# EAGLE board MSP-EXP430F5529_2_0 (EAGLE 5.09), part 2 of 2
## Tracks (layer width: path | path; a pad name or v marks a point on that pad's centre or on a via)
5529_LDO  (via drill 0.3, 0.56)
  Top 0.305: 88.17,30.01 U1.66
  Top 0.61: 88.17,30.01 89.12,30.01 89.84,29.29 C5.1 90.68,26.16 v91.19,26.67 90.42,25.91 C9.1 91.94,24.22 C7.1
  PWR 1.016: v34.04,46.74 34.04,42.42 49.02,27.43 52.83,27.43 58.93,21.34 70.61,21.34 72.14,19.81 88.39,19.81 91.19,22.61 v91.19,26.67
  Bottom 0.254: S4.1 99.82,69.85 99.82,61.72 99.06,60.96 98.04,60.96 95.76,58.67 95.76,37.59 97.54,35.81 97.54,27.69 96.27,26.42 91.44,26.42 v91.19,26.67
  Bottom 1.016: v34.04,46.74 21.08,59.69 18.03,59.69 17.27,60.45 17.27,65.53 JP8.1
5529_VBUS  (via drill 0.3, 0.56)
  Top 0.305: U1.65 86.36,29.52 86.16,29.52 | 30.01,67.95 R19.2 | 29.98,65.86 U4.8
  Top 0.406: 85.39,29.52 86.16,29.52 | 29.9,65.86 29.98,65.86
  Top 0.61: v85.09,29.21 85.39,29.52 | 93.31,56.39 C34.1 95.25,56.22 | v28.96,66.8 29.9,65.86 | 95.25,56.22 C33.1 | v95,57.91 95,56.48 95.25,56.22
  Top 0.813: 28.87,66.8 30.01,67.95 | C27.2 27.93,65.86 28.87,66.8 | 28.87,66.8 v28.96,66.8
  PWR 0.61: 75.18,76.96 76.71,78.49 82.04,78.49 82.8,77.72 81.03,75.95 76.2,75.95 75.18,76.96
  PWR 1.016: v34.54,74.42 38.86,74.42 41.4,76.96 75.18,76.96 | 82.8,77.72 91.69,77.72 94.49,74.93 94.49,65.53 96.77,63.25 JP15.1
  Bottom 0.61: v85.09,29.21 85.09,32.26 87.88,35.05 88.9,35.05 92.71,38.86 94.64,38.86 95,39.22 v95,57.91 95,59.69 97.79,62.48 JP15.1
  Bottom 1.016: v28.96,66.8 34.54,72.39 v34.54,74.42
A5  (via drill 0.3)
  Top 0.254: v99.06,40.89 98.3,41.66 88.9,41.66 87.38,40.13 85.85,40.13 85.6,40.39 84.84,40.39 84.51,40.06 U1.2 | v102.11,37.85 102.11,20.83 108.46,14.48 108.46,8.3 POT1.2
  Bottom 0.254: v102.11,37.85 v99.06,40.89
ACCEL_CS
  Top 0.254: U1.42 76.01,26.35 75.69,26.67 74.93,26.67 72.89,24.63 U2.7
ACCEL_INT
  Top 0.254: U1.34 74.9,30.51 75.69,29.72 75.69,28.19 72.63,25.13 U2.8
ACCEL_PWR  (via drill 0.3)
  Top 0.305: U1.43 76.51,23.17 74.93,21.59 69.6,21.59 68.33,22.86 v68.33,23.62 68.83,24.13 U2.3 | v68.33,25.65 68.85,25.13 U2.1
  Bottom 0.305: v68.33,23.62 67.82,23.11 C20.1 C21.1 v68.33,25.65
ACCEL_SCK  (via drill 0.3)
  Top 0.254: U1.36 74.89,29.51 v74.93,29.46 | v74.68,23.37 73.66,23.37 73.39,23.63 U2.5
  Bottom 0.254: v74.93,29.46 74.42,29.46 73.66,28.7 73.66,25.91 74.68,24.89 v74.68,23.37
ACCEL_SIMO  (via drill 0.3)
  Top 0.254: v73.91,24.13 U2.6
  Top 0.305: U1.40 72.72,27.51 72.39,27.18 72.39,26.92 72.64,26.67 v72.9,26.67
  Bottom 0.254: v72.9,26.67 72.9,25.15 v73.91,24.13
ACCEL_SOMI
  Top 0.254: U1.41 75.51,22.94 74.68,22.1 69.85,22.1 69.09,22.86 69.09,23.37 69.35,23.63 U2.4
ALT_LDO  (via drill 0.3)
  Top 0.406: U4.1 30.01,61.26 v29.46,60.71
  Top 0.813: v29.46,60.71 28.02,60.71 C28.2
  Bottom 1.016: SW1.1 6.86,76.2 12.45,70.61 20.83,70.61 JP8.3 24.13,66.04 v29.46,60.71
AVCC  (via drill 0.3)
  Top 0.305: U1.11 80.01,38.1
  Top 0.406: 80.01,38.1 80.52,37.59 85.85,37.59 v86.11,37.85
  Bottom 0.406: v86.11,37.85 87.31,39.05 C13.1 | C13.1 87.38,39.37 R2.1 | C50.+ 88.57,40.24 C13.1
BRXD  (via drill 0.3)
  Top 0.254: R35.2 9.91,49.28 v7.87,51.31 | U8.10 5.7,55.77 v5.59,55.88 4.06,55.88 2.66,57.28 J17.6
  Bottom 0.254: v7.87,51.31 7.87,53.59 v5.59,55.88
BRXDI  (via drill 0.3)
  Top 0.254: v13.72,43.69 13.75,43.72 U7.35 13.75,46.19 13.46,46.48 10.92,46.48 9.91,47.5 R35.1 | v9.14,24.38 8.89,24.13 8.89,22.35 6.34,19.81 U10.32 5.35,19.32 3.3,17.27 R45.1
  Bottom 0.254: v13.72,43.69 11.94,43.69 8.38,40.13 8.38,25.65 9.14,24.89 v9.14,24.38
BTXD  (via drill 0.3)
  Top 0.254: R36.2 10.92,49.78 8.64,52.07 6.86,52.07 5.72,50.93 J17.1 | v4.83,55.12 U8.11
  Bottom 0.254: v4.83,55.12 4.83,53.8 4.83,52.83 2.93,50.93 J17.1
BTXDI  (via drill 0.3)
  Top 0.254: R36.1 10.92,47.5 11.43,46.99 13.97,46.99 v14.22,46.74 14.25,46.71 U7.34 | v8.13,24.38 8.13,22.61 6.13,20.61 U10.31 4.6,20.61 4.32,20.32 4.32,19.3 2.29,17.27 R44.1
  Bottom 0.254: v14.22,46.74 7.87,40.39 7.87,25.4 8.13,25.15 v8.13,24.38
CB0  (via drill 0.3)
  Top 0.254: U1.77 86.31,35.51 85.85,35.05 83.82,35.05 82.8,36.07 v82.8,36.32 | PAD1.1 v41.4,12.19
  Bottom 0.254: v82.8,36.32 82.8,35.05 82.04,34.29 75.35,34.29 70.1,29.04 70.1,18.24 69.39,17.53 45.72,17.53 44.11,15.91 R14.2
  Bottom 0.305: R14.2 41.66,12.45 v41.4,12.19
CB1  (via drill 0.3)
  Top 0.254: U1.78 86.05,36.01 85.6,35.56 84.07,35.56 83.57,36.07 v83.57,36.83 | PAD2.1 v52.58,12.19
  Bottom 0.254: v83.57,36.83 83.57,35.05 82.3,33.78 75.69,33.78 70.61,28.7 70.61,17.93 69.7,17.02 56.39,17.02 55.37,16 55.37,12.53 R15.2
  Bottom 0.305: R15.2 52.83,12.45 v52.58,12.19
CB2  (via drill 0.3)
  Top 0.254: U1.79 85.78,36.51 85.34,36.07 84.58,36.07 v84.33,36.32 | PAD3.1 v63.75,12.19
  Bottom 0.254: v84.33,36.32 84.33,35.05 82.55,33.27 75.95,33.27 71.12,28.45 71.12,17.02 69.34,15.24 67.82,15.24 66.46,13.88 R16.1
  Bottom 0.305: R16.1 64.01,12.45 v63.75,12.19
CB3  (via drill 0.3)
  Top 0.254: U1.80 85.27,37.01 v85.09,36.83 | PAD4.1 v74.93,12.19
  Bottom 0.254: v85.09,36.83 85.09,35.01 82.85,32.77 76.2,32.77 71.63,28.19 71.63,17.02 74.93,13.72 v74.93,12.19 | 77.72,12.53 R12.2 77.22,12.45
  Bottom 0.305: 77.22,12.45 75.18,12.45 v74.93,12.19
CB4  (via drill 0.3)
  Top 0.254: 85.01,39.29 85.34,39.62 85.6,39.62 85.85,39.37 v85.85,38.86 85.34,38.86 85.09,39.12 85.06,39.08 U1.1 | v86.11,12.19 PAD5.1
  Bottom 0.254: v85.85,38.86 85.09,38.1 85.09,37.85 85.85,37.08 85.85,35.01 83.1,32.26 76.45,32.26 72.14,27.94 72.14,17.48 73.62,16 85.6,16 86.11,15.49 v86.11,12.19
  Bottom 0.305: R13.2 86.36,12.45 v86.11,12.19
CBOUT  (via drill 0.3)
  Top 0.254: v46.99,12.95 v58.17,12.95 v69.34,12.95 v80.52,12.95 v91.69,12.95 | U1.27 61.69,34.01 54.61,26.92 54.61,18.54 57.15,16 v58.17,16
  Bottom 0.254: R14.1 45.81,12.53 46.57,12.53 v46.99,12.95 | 56.98,12.53 R15.1 57.66,12.45 v58.17,12.95 v58.17,16 | R16.2 68.16,12.53 68.92,12.53 v69.34,12.95 | 79.34,12.53 R12.1 80.01,12.45 v80.52,12.95 | R13.1 90.51,12.53 91.27,12.53 v91.69,12.95
CLK3410  (via drill 0.3)
  Top 0.254: U7.49 5.2,43.82 v5.08,43.94 | v1.52,21.34 R49.2
  Bottom 0.254: v5.08,43.94 5.08,33.53 1.52,29.97 v1.52,21.34
D1A  (via drill 0.3)
  Top 0.254: 25.15,27.69 25.14,27.69 U5.4 | U5.3 24.64,28.19 25.27,27.56
  Top 0.61: v30.99,24.13 28.7,24.13 25.27,27.56 25.15,27.69
  Bottom 0.406: 31.08,24.03 v30.99,24.13
  Bottom 0.61: U3.1 31.08,24.03
D1B  (via drill 0.3, 0.56)
  Top 0.254: U5.7 25.14,33.52 25.91,34.29 25.71,34.29 24.64,33.21 U5.8
  Top 0.61: 25.91,34.29 27.94,34.29 v39.62,22.61 | U3.14 59.87,20.32 v57.15,20.32
  Bottom 0.61: v57.15,20.32 41.91,20.32 v39.62,22.61
DVCC  (via drill 0.56, 1.4)
  Top 0.254: R1.2 89.32,46.48 v87.88,46.48
  Top 0.305: 80.26,24.13 80.01,24.38 80.01,24.64 U1.50 80.01,27.94 | 76.51,38.16 U1.18
  Top 0.406: v81.28,23.88 80.52,23.88 80.26,24.13 | v78.49,29.46 80.01,27.94 | 76.51,38.16 76.51,37.79 v76.71,37.59
  PWR 0.813: JP6.2 29.97,78.23 29.21,78.99 26.16,78.99 22.1,74.93 22.1,71.37 20.83,70.1 18.54,70.1 17.02,68.58 17.02,67.06 21.59,62.48 JP11.2 21.59,56.64 JP16.9
  Bottom 0.406: v78.49,29.46 78.49,27.51 C15.+ 78.56,25.29 C16.2 | C12.1 80.84,24.32 v81.28,23.88 | R2.2 91.19,39.37 v92.2,40.39 92.37,40.55 C11.2 | v87.88,46.48 C10.+
  Bottom 0.61: 55.37,52.58 55.37,55.12 54.86,55.63 | 52.07,55.63 52.58,55.12 52.58,53.09 53.09,52.58
  Bottom 1.016: 54.86,55.63 52.07,55.63 48.01,55.63 40.89,62.74 40.89,70.87 35.05,76.71 JP6.2 | 53.09,52.58 55.37,52.58 62.61,45.34 | 62.61,45.34 63.25,44.7 v63.25,44.2 | v64.01,45.47 62.74,45.47 62.61,45.34
  Bottom 1.27: JP6.2 31.24,76.71 v34.04,79.5
  pour PWR (isolate 0.305): 85.6,25.15 83.05,22.1 78.5,22.1 61.72,38.88 61.72,45.15 63.31,46.74 64.77,46.74 71.88,39.62 77.41,39.62 arc-90 77.98,39.06 77.98,38.92 arc90 78.55,38.35 80.71,38.35 arc90 81.28,38.92 81.28,41.91 87.38,48.01 93.98,48.01 93.98,39.22 88.79,34.04 86.68,34.04 arc90 85.6,32.96
DVCC_SW  (via drill 1.4)
  Top 1.27: SW1.7 4.73,72.14 7.11,72.14 11.43,76.45 11.43,78.99 12.45,80.01 23.11,80.01 v23.62,79.5
  Bottom 1.27: v23.62,79.5 24.64,79.5 JP6.1
EZ_D+
  Top 0.254: USB2.D+ 7.89,7.35 8.89,6.35 10.42,6.35 R43.1 11.69,5.34 12.95,6.6 12.95,7.62 11.95,8.63 U11.5
EZ_D-  (via drill 0.3)
  Top 0.254: U11.3 9.39,7.63 v9.14,7.87 | v15.24,12.7 R46.1
  Bottom 0.254: USB2.D- 6.6,8.26 6.6,9.4 7.37,10.16 8.64,10.16 9.14,9.65 v9.14,7.87 9.4,7.62 15.24,7.62 16.26,8.64 16.26,11.68 16,11.94 v15.24,12.7
EZ_VBUS
  Top 0.305: U11.1 8.23,8.63 USB2.VBUS
  Top 0.406: U9.6 U9.5 12.85,11.18 | 12.85,11.18 12.45,11.18 12.45,10.92 13.72,10.92 13.72,11.18 12.85,11.18 | TP9.1 10.67,11.18 11.18,11.68 C43.2
  Top 0.813: USB2.VBUS 7.89,9.16 TP9.1 12.45,11.18
EZ_VCC  (via drill 0.3, 0.56)
  Top 0.254: 4.6,35.31 6.35,35.31 7.11,34.54 | 7.11,32.92 7.11,34.54 | 7.11,34.54 7.25,34.54
  Top 0.305: U7.1 7.25,34.54 7.25,34.66 v6.86,35.05 6.37,35.54 U7.64
  Top 0.406: U9.7 11.61,10.08 v11.18,9.65 11.39,9.44 U9.8 | R33.2 R37.2 14.99,7.11 14.73,7.37 v14.73,9.65 | R40.2 C41.1 | C40.2 15.02,16.76 C41.1 | C41.1 13.46,17.53 v13.72,17.78 | v8.89,19.81 8.45,19.37 U10.3 8.45,17.34 R47.2 C47.2 | v2.29,14.99 R44.2 R45.2 | C48.2 C49.1 2.29,24.9 v3.3,25.91 3.8,25.41 U10.25 | U10.23 U10.24 6.62,26.91 v5.84,27.69 | v5.84,27.69 5.33,27.18 5.33,25.65 | 5.84,27.94 5.84,28.11 U12.8 3.51,28.49 R54.1 R53.1 | 5.84,27.94 v5.84,27.69 | 5.84,27.94 5.33,28.45 | C42.1 4.09,34.01 v4.06,34.04 | R39.2 16.76,21.85 v16.51,22.1 15.76,22.85 R28.2 | v5.84,52.58 6.43,53.17 U8.14 | R30.2 v16,49.78
  Top 0.813: v11.18,9.65 v14.73,9.65
  Top 1.016: SW1.2 SW1.6 v2.8,72.65 v2.79,72.64
  pour PWR (isolate 0.406): 0.76,0.76 0.76,77.22 8.13,77.22 8.13,58.17 17.53,58.17 17.53,0.76
GND  (via drill 0.3, 0.56, 1.4)
  Top 0.305: U1.19 76.01,40.2 v76.2,40.39 | R21.1 25.56,38.19 C30.1 | v6.86,36.83 6.57,36.54 | v76.96,27.43 78.49,27.43 79.51,26.4 U1.49 79.5,23.37 79.76,23.11 80.01,23.11 | 5.42,36.32 U7.62 U7.63 | U4.2 30.66,63.49 U4.PP@2 | 28.96,64.26 U4.PP@1 | U4.PP@1 33.27,64.26 | U4.PP@1 U4.TH@2 | v85.85,27.43 85.93,27.51 U1.61 | C5.2 87.96,27.36 87.81,27.51 U1.61 | U4.PP@4 31.31,65.04 U4.6 31.31,66.73 v30.99,67.06 30.66,66.73 U4.7 30.66,65.04 U4.PP@5 | U2.2 v68.08,24.63 v68.07,24.64 | U4.4 31.96,63.39 U4.PP@3 | U1.14 78.51,38.13 77.98,37.59 v77.72,37.59 | U1.68 84.6,31.01 v84.07,30.48 | C19.1 50.55,61.72 | U1.61 | 6.38,36.3 6.48,36.4 6.48,36.45 | U5.5 25.64,31.15 U5.P$3
  Top 0.406: v4.32,12.95 4.06,13.21 R48.1 | C43.1 9.14,12.45 v8.89,12.7 | U12.4 U12.1 12.07,29.59 | U10.18 11.65,25.18 v11.68,25.15 | U10.15 13.95,25.89 v14.22,26.16 | C37.2 v15.76,25.9 v15.75,25.91 | U10.8 12.45,19.3 v11.43,20.32 | U9.4 U9.3 | C45.1 11.68,3.3 v11.94,3.05 | U10.28 6.5,23.01 v6.6,23.11 | C48.1 v3.29,22.36 v3.3,22.35 | R51.2 3.29,19.31 3.3,19.3 v2.79,18.8 | X1.A 59,66.22 | v69.34,77.98 RF2.2 | C34.2 93.56,54.52 | 6.35,36.32 5.42,36.32 | U12.7 4.39,29.14 v4.32,29.21 | U8.7 13.89,57.07 v13.97,57.15 11.43,57.15 v11.18,56.9 11.94,56.9 12.19,57.15 12.7,57.15 | v17.78,17.53 15.77,17.53 C44.2 | C38.2 3.06,45.72 v1.78,45.72
  Top 0.61: 6.35,36.32 6.48,36.45 v6.86,36.83 | 50.55,61.72 50.29,61.98 v50.29,62.99
  Top 0.813: 4.65,36.3 6.38,36.3 | v103.89,58.42 107.19,58.42 J1.9
  GND 0.813: J1.9 107.19,58.42 v103.89,58.42 | v34.29,1.27 28.7,1.27 28.19,1.78 v28.19,3.3
  other vias: 1.52,49.53 8.38,47.24 12.45,49.53 1.52,32.26 13.21,30.73 16.51,13.21 14.73,6.1 28.19,10.41 28.19,6.86 22.35,24.13 25.65,39.62 35.05,60.2 62.99,55.63 43.69,65.53 91.44,50.04 97.79,72.14 99.31,44.96 100.84,54.36 60.45,43.18 22.35,32 28.7,31.75 4.06,24.64 61.95,19.99 65.28,24.38 32,34.29 9.14,78.99 23.37,70.87 34.04,64.26 33.78,67.31 26.42,58.67 6.6,64.26 2.03,66.04 23.11,39.62 9.91,21.34 16,28.19 15.24,11.18 16.26,46.74 16.51,55.63 32.77,20.07 39.88,25.91 52.07,24.64 49.02,16.51 41.4,16.51 96.52,7.62 97.79,2.54 102.62,18.54 97.54,21.08 88.9,37.59 93.47,44.45 56.9,46.99 60.96,52.07 38.35,56.64 36.32,46.74 61.98,78.49 38.1,60.71 33.27,75.18 93.73,79.5 92.46,68.58 109.47,41.15 57.4,26.16 1.52,1.52 1.52,79.76 110.24,79.76 110.24,1.52 36.32,79.76 6.86,38.35 70.87,80.01 34.29,25.15 100.58,50.04 105.41,70.36 87.88,44.96 49.28,42.67 84.58,16.76 11.68,6.6 10.67,29.46 41.91,58.67 101.09,75.69 101.85,67.56 93.22,57.4 80.52,22.1 72.39,45.47 93.73,53.09 97.79,12.7 90.17,18.29 60.96,58.67 54.61,62.99 63.5,75.69 64.26,70.87 57.66,62.99 28.19,64.52 28.19,69.09 11.94,74.42 18.54,36.83 88.39,53.09 68.55,27.1 72.87,22.78 3.56,57.91
  pour GND (isolate 0.406, rank 2): 0.76,0.76 0.76,80.52 111,80.52 111,61.21 104.9,61.21 104.9,55.88 102.62,55.88 102.62,41.91 111,41.91 111,20.57 109.22,20.57 109.22,12.45 111,12.45 111,0.76 95.25,0.76 95.25,14.73 29.21,14.73 29.21,0.76
  pour Top (isolate 0.406, rank 2): 0.76,0.76 0.76,80.52 111,80.52 111,61.21 104.9,61.21 104.9,55.88 102.62,55.88 102.62,41.91 111,41.91 111,20.57 109.22,20.57 109.22,12.45 111,12.45 111,0.76
  pour Bottom (isolate 0.406, rank 2): 0.76,0.76 0.76,80.52 111,80.52 111,61.21 104.9,61.21 104.9,55.88 102.62,55.88 102.62,41.91 111,41.91 111,20.57 109.22,20.57 109.22,12.45 111,12.45 111,0.76 99.82,0.76 99.82,15.24 29.21,15.24 29.21,0.76
  pour Bottom (isolate 0.406, hatched): 28.96,0.76 28.96,15.49 100.08,15.49 100.08,0.76
HTCK
  Top 0.254: U7.57 3.73,39.04 2.29,37.59 TP12.1
HTDI
  Top 0.254: U7.55 3.39,40.04 2.29,41.15 TP14.1
HTDO
  Top 0.254: U7.54 3.91,40.54 3.56,40.89 3.56,43.43 2.79,44.2 TP15.1
HTMS
  Top 0.254: U7.56 2.71,39.54 TP13.1
ISET
  Top 0.254: R21.2 23.11,34.29 23.64,33.77 U5.10
JTAG_PWR  (via drill 0.3)
  Top 1.016: SW1.8 SW1.4 6.73,68.2 15.24,59.69 15.37,59.69 20.83,59.69 32,48.51 v34.8,48.51
  PWR 1.016: v34.8,48.51 65.02,48.51 68.07,51.56 101.35,51.56 J1.2
JTAG_SENSE  (via drill 0.3)
  PWR 0.61: J1.4 104.39,51.05 104.39,54.1 103.12,55.37 87.88,55.37 85.6,53.09 67.31,53.09 64.52,50.29 v32.26,50.29
  Bottom 0.61: v32.26,50.29 32.26,50.8 24.13,58.93 JP11.1
LCD_BL_EN  (via drill 0.3)
  Top 0.254: v59.69,23.11 60.2,23.11 66.8,16.51 78.74,16.51 84.51,22.28 U1.59 | v36.58,23.37 27.94,23.37 24.38,26.92 23.96,26.92 R20.2 | R20.2 23.96,27.01 24.13,27.18 U5.2 | U5.1 23.64,27.25 R20.2
  Bottom 0.254: v36.58,23.37 59.44,23.37 v59.69,23.11
LCD_CS  (via drill 0.3)
  Top 0.254: v58.93,24.13 59.18,23.88 60.2,23.88 67.06,17.02 78.49,17.02 83.51,22.05 U1.57 | U3.28 32.35,55.44 R18.2
  Bottom 0.254: v58.93,24.13 58.93,35.05 46.74,47.24 38.02,47.24 U3.28
LCD_D/C  (via drill 0.3)
  Top 0.254: v60.45,26.16 60.96,25.65 60.96,24.64 67.56,18.03 77.98,18.03 82.51,22.57 U1.55
  Bottom 0.254: v60.45,26.16 60.45,36.07 47.24,49.28 41.07,49.28 U3.26
LCD_RST  (via drill 0.3)
  Top 0.254: v59.69,25.15 67.31,17.53 78.23,17.53 83.01,22.31 U1.56 | U3.27 34.71,55.27 R17.2
  Bottom 0.254: v59.69,25.15 59.69,35.56 46.99,48.26 39.55,48.26 U3.27
LDO_SEL
  Bottom 1.016: SW1.5 3.81,76.2 4.57,75.44 4.57,73.15 5.33,72.39 7.87,72.39 11.43,68.83 20.07,68.83 JP8.2
LFXTGND  (via drill 0.3)
  Top 0.254: Q1.P3 78.26,51.48 v78.26,43.56
  Top 0.305: v78.26,42.04 78.51,41.78 78.51,38.91
  Bottom 0.406: C4.2 C2.2 78.26,46.41 v78.26,43.56 v78.26,42.04
  pour Top (isolate 0.305, no thermals, hatched): 75.5,42.93 75.18,43.18 75.18,52.58 75.65,53.09 80.82,53.09 81.53,52.37 81.53,44.2 80.26,42.93
  pour Bottom (isolate 0.305): 77.98,38.61 77.98,40.39 75.18,43.18 75.18,52.58 75.65,53.09 80.82,53.09 81.53,52.37 81.53,41.66 80.26,40.39 80.26,38.61
  pour GND (isolate 0.305): 77.98,38.61 77.98,40.39 75.18,43.18 75.18,52.58 75.65,53.09 80.82,53.09 81.53,52.37 81.53,41.66 80.26,40.39 80.26,38.61
MSP_D+
  Top 0.254: R23.2 102.36,59.69 102.62,59.94 102.62,72.41 USB1.D+
  Bottom 0.305: U6.5 102.86,72.65 USB1.D+
MSP_D-  (via drill 0.3)
  Top 0.254: R22.2 97.79,53.85 98.3,54.36 v99.82,54.36
  Top 0.305: v101.09,74.68 101.6,74.68 103.38,76.45 104.9,76.45 106.17,75.18 106.17,73.91 105.12,72.86 USB1.D-
  Bottom 0.254: v99.82,54.36 99.82,58.17 104.39,62.74 104.39,70.87 105.07,71.54 USB1.D-
  Bottom 0.305: U6.3 100.7,74.28 v101.09,74.68
N$1  (via drill 0.3)
  Top 0.254: U7.47 7.75,46.11 8.13,46.48 v9.4,46.48 | v11.94,47.75 R29.1 R31.1
  Bottom 0.254: v9.4,46.48 10.67,46.48 v11.94,47.75
N$2  (via drill 0.3)
  Top 0.254: U7.46 8.25,44.07 8.38,43.94 8.75,43.94 | U7.43 9.75,44.04 9.65,43.94 8.89,43.94 | 8.75,43.94 U7.45 | 8.89,43.94 8.75,43.94 | 8.89,43.94 8.89,40.39 10.67,38.61 v13.46,38.61 | v15.49,39.12 15.57,39.04 U7.24 17.7,39.04 18.03,39.37 18.03,43.69 14.99,46.74 R32.1 R30.1
  Bottom 0.254: v13.46,38.61 14.99,38.61 v15.49,39.12
N$3
  Top 0.254: U10.27 4.5,23.81 4.32,23.62 4.32,21.59 4.06,21.34 R49.1 3.55,20.82 3.3,20.57 2.54,20.57 2.29,20.32 R51.1
N$4
  Top 0.254: U9.1 17.54,9.41 17.53,9.4 17.53,8.9 R38.2 R37.1
N$5
  Top 0.254: R41.1 4.77,17.21 D2.A 6.03,17.21 6.86,18.03 U10.1
N$6  (via drill 0.3)
  Top 0.254: U10.2 7.62,18.34 v7.62,19.56 | v5.84,14.22 5.59,14.48 D2.C
  Bottom 0.254: v5.84,14.22 6.35,14.22 7.62,15.49 v7.62,19.56
N$7
  Bottom 0.254: R10.2 70.52,9.99 71.97,8.55 LED7.A
N$8
  Bottom 0.254: R8.2 48.17,9.99 49.62,8.55 LED5.A
N$9
  Top 0.254: U10.12 15.13,22.21 15.75,21.59 15.75,21.09 R39.1
N$10
  Bottom 0.254: R9.2 59.35,9.99 60.79,8.55 LED6.A
N$11
  Bottom 0.254: R7.2 37,9.99 38.44,8.55 LED4.A
N$12
  Bottom 0.254: CON1.6 51.56,34.63 51.56,33.27 50.8,32.51 33.78,32.51 24.38,23.11 23.37,23.11 22.1,21.84 22.1,18.54 22.86,17.78 TP7.1
N$13
  Bottom 0.254: R11.2 81.7,9.99 83.14,8.55 LED8.A
N$14
  Top 0.305: U4.5 31.96,67.95 R19.1
N$15
  Top 0.254: U8.2 12.84,53.85 13.72,53.85 15.75,51.82 15.75,51.05 17.02,49.78 17.02,46.99 JP16.2
N$16  (via drill 0.3)
  Top 0.254: v6.6,25.91 9.65,25.91 10.92,24.64 10.92,23.88 13.39,21.41 U10.11 | v4.32,26.67 3.81,27.18 R52.2
  Bottom 0.254: v4.32,26.67 5.84,26.67 v6.6,25.91
N$17
  Top 0.254: R47.1 8.38,15.76 8.38,15.75 8.64,16 8.64,16.51 8.88,16.76 R50.2 9.4,17.27 9.25,17.42 U10.4
N$19
  Top 0.305: R33.1 16.76,5.58 16.26,5.08 16.26,3.83 LED9.A
N$20
  Bottom 0.254: CON1.4 54.23,32.64 53.34,31.75 33.78,31.75 23.37,21.34 TP5.1
N$21
  Top 0.254: LED3.A 31.5,2.79 32.35,1.94 R5.2
N$22
  Top 0.406: USB2.GND@1 2.29,11.52 R48.2
  Top 0.61: USB2.GND@2 USB2.GND@1
N$23
  Top 0.254: U8.3 14.11,54.47 17.02,51.56 17.02,50.55 18.29,49.28 JP16.4
N$24
  Top 0.813: D1.C 97.97,65.96 JP15.2
N$25
  Top 0.254: U8.4 14.48,55.12 18.29,51.31 JP16.6
N$26
  Top 0.254: U10.5 10.05,17.63 10.41,17.27 R42.2
N$27
  Bottom 0.254: CON1.2 56.77,32.13 55.63,30.99 33.78,30.99 24.89,22.1 24.89,16 TP3.1
N$28
  Bottom 0.254: CON1.1 56.77,28.07 55.88,27.18 32.26,27.18 28.96,23.88 28.96,17.02 TP4.1
N$29
  Bottom 0.254: CON1.3 54.23,28.32 53.59,27.69 32,27.69 28.45,24.13 28.45,19.81 TP6.1
N$30
  Top 0.254: U10.7 11.65,15.02 12.95,13.72 C46.2 R46.2
N$31  (via drill 0.3)
  Top 0.254: U10.6 10.85,17.6 11.18,17.27 11.18,16 10.92,15.75 10.91,15.76 R42.1 10.41,15.24 v11.68,13.97 | C45.2 R43.2 13.36,5.08 13.72,5.44 v13.72,8.64
  Bottom 0.254: v13.72,8.64 13.72,11.94 v11.68,13.97
N$32
  Top 0.254: LED1.A 31.5,9.91 32.35,9.06 R3.2
N$33
  Top 0.254: U8.5 14.84,55.77 17.27,53.34 JP16.8
N$34
  Top 0.254: 10.92,58.17 6.09,58.17 R34.2 5.66,57.07 U8.8
  Top 0.406: U8.1 11.6,53.17 10.16,54.61 10.16,57.66 10.67,58.17 10.92,58.17 17.02,58.17 18.29,56.9 JP16.10
N$35
  Top 0.254: LED2.A 31.5,6.35 32.35,5.5 R4.2
N$36  (via drill 0.3)
  Top 0.254: JP3.2 92.71,19.81 92.71,19.56 89.15,16 66.55,16 64.26,18.29 v63.5,18.29 | R3.1 | R3.1 v32.77,11.94
  Bottom 0.254: v63.5,18.29 39.12,18.29 v32.77,11.94
N$38
  Bottom 0.254: CON1.7 33.06,29.5 27.69,24.13 27.69,22.35 TP8.1
N$39
  Top 0.61: USB1.GND@1 USB1.GND@2 108.55,77.72 102.11,77.72
  Top 0.813: 102.11,77.72 R27.2
N$40
  Top 0.254: R26.2 98.64,76.03 S4.2
N$41  (via drill 0.3)
  Top 0.254: C25.1 54.61,57.23 v54.61,58.42
  Bottom 0.254: v54.61,58.42 57.15,55.88 60.45,55.88 61.56,54.77 U3.16
N$42  (via drill 0.56)
  Top 0.813: D1.A v100.84,61.21
  Bottom 0.305: U6.1 100.34,72.65 100.08,72.39 100.08,72.14 100.33,71.88 103.69,71.88 USB1.VBUS
  Bottom 0.813: USB1.VBUS 103.12,71.32 103.12,62.99 101.35,61.21 v100.84,61.21
N$43
  Top 0.254: JP2.1 102.99,17.27 POT1.1
N$44
  Top 0.254: U3.19 53.94,54.77 52.65,56.06 C25.2
N$45
  Top 0.254: U3.17 58.85,54.35 C26.1
N$46
  Top 0.254: U3.18 56.97,54.67 C26.2
N$50
  Top 0.305: U4.3 31.31,61.98 31.83,61.47 C29.2
P1.0  (via drill 0.3)
  Top 0.254: v80.52,29.21 80.52,33.78 v78.23,36.07 | U1.21 74.5,37.01 74.93,36.58 v74.93,36.07 | v85.85,24.38 85.85,18.54 v86.61,17.78 | v69.6,62.74 71.12,61.21 72.14,61.21 73.91,62.99 76.2,62.99 J12.3 | v69.09,70.36 RF2.13
  Bottom 0.254: v85.85,24.38 84.33,25.91 84.33,26.92 83.31,27.94 81.79,27.94 v80.52,29.21 | v74.93,36.07 75.18,35.81 77.98,35.81 v78.23,36.07 78.23,37.08 81.28,40.13 82.04,40.13 83.06,41.15 83.06,60.45 80.52,62.99 78.23,62.99 J12.3 | v86.61,17.78 87.12,18.29 89.15,18.29 92.2,21.34 93.98,21.34 JP3.1 | v69.6,62.74 68.58,62.74 67.31,64.01 67.31,68.58 v69.09,70.36
P1.1  (via drill 0.3)
  Top 0.254: v39.88,13.72 39.88,17.02 59.37,36.51 U1.22
  Bottom 0.254: R7.1 38.61,12.79 38.61,13.72 38.86,13.97 39.62,13.97 v39.88,13.72
P1.2  (via drill 0.3)
  Top 0.254: U1.23 60.2,36.01 51.05,26.86 v51.05,13.72
  Bottom 0.254: R8.1 49.78,12.79 49.78,13.72 50.04,13.97 50.8,13.97 v51.05,13.72
P1.3  (via drill 0.3)
  Top 0.254: U1.24 60.96,35.51 53.09,27.63 53.09,17.78 56.9,13.97 61.98,13.97 v62.23,13.72
  Bottom 0.254: R9.1 60.96,12.79 60.96,13.72 61.21,13.97 61.98,13.97 v62.23,13.72
P1.4  (via drill 0.3)
  Top 0.254: U1.25 61.17,35.01 53.59,27.43 53.59,18.03 57.15,14.48 62.48,14.48 62.99,13.97 73.15,13.97 v73.41,13.72
  Bottom 0.254: R10.1 72.14,12.79 72.14,13.72 72.39,13.97 73.15,13.97 v73.41,13.72
P1.5  (via drill 0.3)
  Top 0.254: v84.58,13.72 84.33,13.97 74.17,13.97 73.66,14.48 63.5,14.48 62.99,14.99 57.4,14.99 54.1,18.29 54.1,27.18 61.43,34.51 U1.26
  Bottom 0.254: R11.1 83.31,12.79 83.31,13.72 83.57,13.97 84.33,13.97 v84.58,13.72
P1.7  (via drill 0.3)
  Top 0.254: U1.28 61.96,33.51 55.12,26.67 55.12,21.34 v55.37,21.08 | v40.89,22.61 36.32,18.03 29.97,18.03 28.45,16.51 28.45,13.97 25.91,11.43 24.89,11.43 24.38,10.92 24.38,4.83 S1.1
  Bottom 0.254: v40.89,22.61 41.66,21.84 54.61,21.84 v55.37,21.08
P2.0  (via drill 0.3)
  Top 0.254: U1.29 70.6,33.01 v70.36,32.77 | v35.05,77.98 35.05,75.95 35.56,75.44 RF1.5 | RF2.15 v64.26,69.09 63.5,68.33 63.5,66.8 59.94,63.25 59.94,56.39 60.96,55.37 62.23,55.37 62.74,54.86 62.74,53.34 63.25,52.83 67.31,52.83 v70.87,56.39
  Bottom 0.254: v35.05,77.98 55.37,77.98 v64.26,69.09 | v70.36,32.77 70.36,55.88 v70.87,56.39 72.9,58.42 73.66,58.42 75.95,60.71 78.49,60.71 J12.4
P2.1  (via drill 0.3)
  Top 0.254: U1.30 71.37,32.51 v71.12,32.26 | v38.61,76.71 RF1.3 | v64.26,67.82 65.53,66.55 65.53,65.53 70.61,60.45 72.9,60.45 v73.15,60.71 73.15,59.94 v74.68,58.42
  Bottom 0.254: v38.61,76.71 55.37,76.71 v64.26,67.82 | v71.12,32.26 71.12,54.86 v74.68,58.42 | J12.14 78.74,73.66 74.42,73.66 73.15,72.39 v73.15,60.71
P2.2  (via drill 0.3)
  Top 0.254: U1.31 71.89,32.01 71.37,31.5 70.61,31.5 70.1,32 61.21,32 55.63,26.42 55.63,22.86 55.63,22.35 v55.88,22.1 | v42.16,22.61 36.83,17.27 30.23,17.27 29.72,16.76 29.72,13.71 S2.1
  Bottom 0.254: v42.16,22.61 55.37,22.61 v55.88,22.1
P2.3  (via drill 0.3)
  Top 0.254: U1.32 72.15,31.51 71.63,30.99 70.36,30.99 69.85,31.5 68.33,31.5 v68.07,31.24 | v42.67,72.9 RF1.10 | v64.26,64.01 64.77,64.01 v69.85,58.93
  Bottom 0.254: J12.13 73.91,74.68 72.39,73.15 72.39,61.47 v69.85,58.93 68.07,57.15 v68.07,31.24 | v42.67,72.9 55.37,72.9 v64.26,64.01
P2.4  (via drill 0.3)
  Top 0.254: U1.33 72.41,31.01 71.88,30.48 69.09,30.48 v68.83,30.73 | v42.67,71.63 RF1.12 | v64.26,62.74 64.77,62.74 v69.72,57.78
  Bottom 0.254: v68.83,30.73 68.83,56.9 v69.72,57.78 71.37,59.44 73.15,59.44 75.18,61.47 75.18,67.06 76.45,68.33 78.49,68.33 J12.10 | v42.67,71.63 55.37,71.63 v64.26,62.74
P4.0  (via drill 0.3)
  Top 0.254: U1.45 77.51,21.13 v77.22,20.83 76.2,19.81 v69.34,19.81 | v42.67,75.44 RF1.6 39.12,75.44 38.61,74.93 38.61,74.42 38.35,74.17 RF1.7 | v69.6,56.64 67.82,58.42 62.48,58.42 61.21,59.69 61.21,63.5 v64.26,66.55
  Bottom 0.254: v69.34,19.81 69.6,20.07 v69.6,56.64 71.88,58.93 73.41,58.93 75.95,61.47 75.95,65.02 76.45,65.53 78.74,65.53 J12.6 | v42.67,75.44 55.37,75.44 v64.26,66.55 | v77.22,20.83 77.98,20.07 88.65,20.07 91.44,22.86 100.33,22.86 J5.9
P4.6  (via drill 0.3)
  Top 0.254: U1.53 81.51,26.9 82.3,27.69 82.3,34.29 80.52,36.07 v80.52,36.83 | v42.67,74.17 RF1.8 39.37,74.17 38.86,73.66 38.86,73.15 38.61,72.9 RF1.9 | v64.26,65.28 64.52,65.28 v69.85,59.94 | v55.12,37.85 56.13,37.85 56.39,37.59 71.12,37.59 71.63,38.1 73.15,38.1 v73.41,37.85 | v71.63,61.98 75.95,66.29 75.95,67.56 76.71,68.33 78.49,68.33 J12.8
  Bottom 0.254: v80.52,36.83 80.52,37.08 82.04,38.61 82.8,38.61 84.58,40.39 84.58,64.52 J4.7 J12.8 | v64.26,65.28 55.37,74.17 v42.67,74.17 | v71.63,61.98 69.85,60.2 v69.85,59.94 | v80.52,36.83 80.52,36.07 | v73.41,37.85 73.41,36.07 74.17,35.31 80.01,35.31 80.52,35.81 v80.52,36.83 | CON3.2 42.42,41.23 42.42,38.61 43.18,37.85 v55.12,37.85
P4.7  (via drill 0.3)
  Top 0.254: U1.54 82.01,26.64 82.8,27.43 82.8,34.54 81.28,36.07 v81.28,36.32 | RF2.18 72.39,67.82 74.17,69.6 J12.9 | v55.63,37.08 71.63,37.08 v71.88,37.34 | v83.82,68.07 83.82,67.82 J4.9
  Bottom 0.254: v71.88,37.34 71.88,36.58 73.66,34.8 80.52,34.8 81.28,35.56 v81.28,36.32 81.28,37.08 82.04,37.85 82.8,37.85 85.09,40.13 85.09,62.48 J4.9 | CON3.1 41.57,37.08 v55.63,37.08 | J12.9 78.49,70.87 80.52,70.87 83.31,68.07 v83.82,68.07
P5.1  (via drill 0.3)
  Top 0.254: U1.10 80.51,42.72 82.5,44.7 82.5,45.67 87.12,50.29 87.12,55.37 v86.11,56.39
  Bottom 0.254: v86.11,56.39 85.6,56.9 85.6,60.45 J4.11
P6.6  (via drill 0.3)
  Top 0.254: v87.12,40.89 86.87,40.64 86.11,40.64 85.6,41.15 84.78,41.15 84.01,40.39 U1.3 | J4.2 88.65,73.66 83.31,73.66 80.52,70.87 v74.68,70.87 | v74.42,68.33 72.64,66.55 RF2.20
  Bottom 0.254: J4.2 90.93,73.41 90.93,58.67 86.61,54.36 86.61,42.16 87.12,41.66 v87.12,40.89 | v74.68,70.87 74.68,68.58 v74.42,68.33
P6.7  (via drill 0.3)
  Top 0.254: v86.36,41.4 86.11,41.66 84.46,41.66 83.51,40.71 U1.4
  Bottom 0.254: J4.14 88.9,58.67 88.9,57.4 86.11,54.61 86.11,41.66 v86.36,41.4
P7.0  (via drill 0.3)
  Top 0.254: v99.82,41.66 99.31,42.16 84.12,42.16 83.01,41.05 U1.5
  Bottom 0.254: v99.82,41.66 103.17,41.66 106.43,38.4 J5.2
P7.1  (via drill 0.3)
  Top 0.254: v100.58,42.42 100.33,42.67 83.81,42.67 82.51,41.38 U1.6
  Bottom 0.254: v100.58,42.42 103.47,42.42 107.7,38.19 107.7,35.31 J5.4
P7.2  (via drill 0.3)
  Top 0.254: U1.7 82.01,41.72 83.47,43.18 v101.35,43.18
  Bottom 0.254: v101.35,43.18 103.73,43.18 108.46,38.45 108.46,33.53 J5.6
P7.3  (via drill 0.3)
  Top 0.254: U1.8 81.51,42.05 83.15,43.69 100.84,43.69 101.09,43.94 v101.85,43.94
  Bottom 0.254: J5.8 109.22,31.75 109.22,38.66 103.94,43.94 v101.85,43.94
P7.5  (via drill 0.3)
  Top 0.254: U1.58 84.01,26.73 83.31,27.43 83.31,34.8 82.04,36.07 v82.04,36.83 | RF2.19 67.31,64.77 68.58,63.5 71.12,63.5 75.44,67.82 v75.44,68.33
  Bottom 0.254: v82.04,36.83 82.55,37.34 83.06,37.34 85.6,39.88 85.6,54.86 88.14,57.4 88.14,67.82 87.63,68.33 85.85,68.33 81.03,73.15 78.23,73.15 J12.11 75.44,70.36 v75.44,68.33
P7.7  (via drill 0.3)
  Top 0.254: v107.19,18.54 107.19,20.57 J5.14 | U1.60 85.01,17.86 v85.34,17.53
  Bottom 0.254: v85.34,17.53 86.36,16.51 91.19,16.51 91.69,16 104.65,16 v107.19,18.54
P8.0  (via drill 0.3)
  Top 0.254: U1.15 78.01,41.11 76.96,42.16 75.69,42.16 v75.44,42.42 | v79.76,29.97 80.01,30.23 80.01,33.27 76.96,36.32 v76.96,36.58 | v85.85,25.4 86.61,24.64 86.61,19.3 v88.65,17.27 | J4.8 90.93,65.79 90.93,61.47 90.17,60.71 84.07,60.71 v82.3,58.93
  Bottom 0.254: v85.85,25.4 84.84,26.42 84.84,27.18 83.57,28.45 82.3,28.45 80.77,29.97 v79.76,29.97 | v88.65,17.27 JP2.2 | v82.3,58.93 82.04,58.67 82.04,57.66 81.28,56.9 75.9,56.9 74.68,55.67 74.68,43.18 v75.44,42.42 75.44,37.59 76.45,36.58 v76.96,36.58
P8.1  (via drill 0.3)
  Top 0.254: U1.16 77.51,40.85 76.71,41.66 v74.17,41.66 | R4.1 32.93,7.37 33.53,7.37 34.04,7.87 34.04,12.95 52.58,31.5 52.58,37.34 54.36,39.12 62.23,39.12 64.01,40.89 65.53,40.89 66.29,40.13 72.39,40.13 v72.64,40.39 | v81.03,61.47 81.03,69.34 84.84,73.15 88.65,73.15 J4.4
  Bottom 0.254: v81.03,61.47 81.03,58.21 80.73,57.91 75.3,57.91 73.66,56.27 73.66,42.16 v74.17,41.66 72.9,40.39 v72.64,40.39
P8.2  (via drill 0.3)
  Top 0.254: U1.17 77.01,40.59 76.45,41.15 74.93,41.15 v74.68,40.89 | R5.1 34.12,3.64 34.54,4.06 34.54,12.7 53.09,31.24 53.09,37.08 54.61,38.61 62.48,38.61 64.01,40.13 65.53,40.13 66.04,39.62 74.42,39.62 v74.68,39.37 | v81.79,60.71 81.79,69.26 83.39,70.87 88.39,70.87 J4.6
  Bottom 0.254: v81.79,60.71 81.79,60.2 81.53,59.94 81.53,57.94 81,57.4 75.59,57.4 74.17,55.98 74.17,42.67 74.93,41.91 74.93,41.15 v74.68,40.89 v74.68,39.37
PU.0/DP  (via drill 0.3)
  Top 0.254: U1.62 88.32,28.01 v88.9,27.43 | R24.2 C36.1 | R25.2 v97.28,57.66 97.45,57.49 R24.2 | R23.1 98.55,58.51 R24.2
  Bottom 0.254: v97.28,57.66 96.27,56.64 96.27,37.85 98.04,36.07 98.04,27.18 96.77,25.91 90.42,25.91 v88.9,27.43
PU.1/DM  (via drill 0.3)
  Top 0.254: C35.1 R22.1 v97.79,50.29 | U1.64 86.16,29.01 v85.34,28.19
  Bottom 0.254: v97.79,50.29 97.28,49.78 97.28,38.35 99.06,36.58 99.06,26.16 97.79,24.89 89.15,24.89 87.12,26.92 87.12,27.69 86.61,28.19 v85.34,28.19
PUR  (via drill 0.3)
  Top 0.254: R25.1 97.37,60.54 | R26.1 96.77,77.56 96.77,68.33 96.01,67.56 96.01,61.81 R25.1 | v98.3,59.69 97.45,60.54 R25.1 | U1.63 88.2,28.51 v88.65,28.96
  Bottom 0.254: v98.3,59.69 98.3,56.9 96.77,55.37 96.77,38.1 98.55,36.32 98.55,26.67 97.28,25.4 89.41,25.4 87.88,26.92 87.88,28.19 v88.65,28.96
RESET  (via drill 0.3)
  Top 0.254: v16.51,26.92 16.76,26.68 C37.1 R28.1 19.3,20.57 19.3,10.67 18.72,10.08 U9.2 | v9.65,32.26 5.59,32.26 4.83,31.5 3.56,31.5 3.3,31.75 3.3,33.27 2.54,34.04 | 2.54,34.04 TP10.1 | 2.54,34.04 3.56,35.05 3.56,38.1 4,38.54 U7.58
  Bottom 0.254: v9.65,32.26 9.65,27.18 9.91,26.92 v16.51,26.92
RF_PWR  (via drill 0.56)
  Top 0.61: J13.2 87,78.36 86.61,77.98 82.55,77.98 82.04,78.49 74.68,78.49 73.91,79.25 v71.88,79.25
  Top 0.813: RF2.9 RF2.7 66.8,73.66 v64.52,73.66 61.89,73.66 C31.1 C32.1
  Top 1.016: J12.2 JP14.2
  PWR 0.813: v64.52,73.66 64.77,73.41 69.09,73.41 72.64,69.85 72.64,63.91 75.85,60.71 78.49,60.71 J12.2
  Bottom 0.61: v71.88,79.25 71.88,78.49 67.06,73.66 v64.52,73.66
RF_SIMO  (via drill 0.3)
  Top 0.254: v42.67,67.82 RF1.18 | v65.79,60.71 v62.74,60.71 | U1.37 65.58,29.01 v65.28,28.7
  Bottom 0.254: J12.18 78.49,78.49 74.42,78.49 65.79,69.85 v65.79,60.71 65.79,29.21 v65.28,28.7 | v62.74,60.71 62.48,60.71 55.37,67.82 v42.67,67.82
RF_SOMI  (via drill 0.3)
  Top 0.254: v42.67,66.55 RF1.20 | v66.55,59.94 v62.23,59.94 | U1.38 66.61,28.51 v66.29,28.19
  Bottom 0.254: J12.15 73.91,77.22 66.55,69.85 v66.55,59.94 66.55,28.45 v66.29,28.19 | v62.23,59.94 61.98,59.94 55.37,66.55 v42.67,66.55
RF_SPI_CLK  (via drill 0.3)
  Top 0.254: U1.39 67.38,28.01 v66.55,27.18 | v42.67,69.09 RF1.16 | v67.31,59.18 v64.01,59.18
  Bottom 0.254: J12.16 78.49,75.95 74.17,75.95 71.88,73.66 71.88,63.75 v67.31,59.18 67.31,27.94 v66.55,27.18 | v64.01,59.18 64.01,60.45 55.37,69.09 v42.67,69.09
RF_STE  (via drill 0.3)
  Top 0.254: U1.35 64.99,30.01 v64.77,30.23 | v42.67,70.36 RF1.14
  Bottom 0.254: v64.77,30.23 65.02,30.48 65.02,60.71 | 65.02,60.71 65.02,69.85 74.93,79.76 J12.17 | v42.67,70.36 55.37,70.36 65.02,60.71
RST3410  (via drill 0.3)
  Top 0.254: U7.42 10.25,40.99 v10.16,40.89 | v9.65,23.37 13.21,19.81 U10.9 15.25,19.81 15.75,19.3 C44.1 v15.75,18.29 | v13.46,14.73 12.95,14.73 12.45,15.24 R40.1 | R41.2 4.32,14.73 v4.83,14.22
  Bottom 0.254: v10.16,40.89 8.89,39.62 8.89,25.91 9.91,24.89 9.91,23.88 9.65,23.62 v9.65,23.37 | v15.75,18.29 15.75,16.26 14.22,14.73 v13.46,14.73 7.87,14.73 6.6,13.46 5.59,13.46 v4.83,14.22
RST/NMI  (via drill 0.3)
  Top 0.254: U1.76 88.14,35.01 88.65,35.52 v88.65,36.07 91.95,39.37 98.55,39.37 104.39,45.21 v104.39,46.23 93.31,46.23 | v76.71,31.5 76.2,32 76.2,36.83 73.91,39.12 71.12,39.12 70.61,38.61 65.02,38.61 v64.26,39.37 | JP16.3 23.88,48.26 31.24,40.89 62.74,40.89 v62.99,41.15 | 93.31,46.23 C3.2 | 93.31,46.23 R1.1
  Bottom 0.254: v76.71,31.5 83.06,31.5 87.63,36.07 v88.65,36.07 | v62.99,41.15 62.99,40.64 v64.26,39.37 | v104.39,46.23 104.39,45.72 106.17,43.94 107.19,43.94 109.73,46.48 109.73,58.42 J1.11
  Bottom 0.406: S3.1 13.46,58.17 18.29,58.17 19.56,56.9 19.56,49.02 20.32,48.26 JP16.3
RXD  (via drill 0.3)
  Top 0.254: U1.52 81.01,27.17 81.79,27.94 81.79,34.04 79.76,36.07 v79.76,36.32 | JP16.5 23.88,50.8 29.97,44.7 v46.23,44.7 57.66,44.7 63.5,50.55 69.09,50.55 76.71,58.17 77.72,58.17 78.74,59.18 78.74,65.53 J12.7 | v47.75,38.61 v47.75,36.32 | v83.57,63.25 83.82,63.5 88.65,63.5 J4.10
  Bottom 0.254: v79.76,36.32 79.76,37.08 81.79,39.12 82.55,39.12 84.07,40.64 84.07,62.74 v83.57,63.25 80.77,66.04 78.23,66.04 J12.7 | CON1.8 47.75,35.9 v47.75,36.32 | v47.75,38.61 46.23,40.13 v46.23,44.7 | J4.10 88.65,65.53 88.65,70.61 J4.3 88.39,73.41 88.39,75.95 89.92,77.47 91.44,77.47 92.08,78.11 J13.6
SBWTCK
  Top 0.254: J17.3 2.31,53.82 U8.13 | 7.11,53.85 7.62,53.85 10.41,51.05 12.95,51.05 13.97,50.04 R31.2
  Top 0.305: U8.13 7.08,53.82 7.11,53.85
SBWTDIO
  Top 0.254: J17.4 2.23,54.47 U8.12 7.76,54.47 10.67,51.56 13.21,51.56 14.99,49.78 R32.2
SCL  (via drill 0.3)
  Top 0.254: U7.31 15.63,42.54 v15.49,42.67 | R52.1 2.29,27.94 4.32,27.94 v4.57,27.69 | v11.68,32.26 9.21,29.79 U12.6 4.64,29.79 4.32,30.11 v4.32,30.23
  Top 0.406: 2.29,27.94 R54.2 | 2.29,27.94 R52.1 2.29,27.93 2.29,27.94
  Bottom 0.254: v15.49,42.67 11.68,38.86 v11.68,32.26 | v4.57,27.69 3.56,28.7 3.56,29.46 v4.32,30.23
SCLK  (via drill 0.3)
  Top 0.254: U1.48 79.01,23.09 79.5,22.61 79.5,22.1 78.99,21.59 78.99,20.83 77.47,19.3 v77.47,18.8 77.22,18.54 67.82,18.54 61.72,24.64 61.72,26.67 v61.21,27.18 | U3.25 38.7,53.75 40.39,52.07 v45.47,52.07 48.26,52.07 49.53,50.8 50.55,50.8 52.83,53.09 52.83,54.86 51.31,56.39 51.31,58.17 53.59,60.45 53.59,64.45 X1.5
  Bottom 0.254: v77.47,18.8 77.72,19.05 89.15,19.05 91.95,21.84 102.62,21.84 103.38,22.61 104.39,22.61 105.16,23.37 105.16,27.94 104.14,28.96 J5.7 | v61.21,27.18 61.21,36.58 45.72,52.07 v45.47,52.07
SD_CS  (via drill 0.3)
  Top 0.254: U1.44 77.01,21.64 v76.2,20.83 75.95,20.57 67.31,20.57 63.25,24.64 63.25,28.7 v62.74,29.21 | v50.04,51.82 50.04,59.44 49.53,59.94 49.53,61.72 49.19,62.06 R6.2 48.35,62.06 50.29,64.01 50.29,64.45 X1.2
  Bottom 0.254: v76.2,20.83 77.47,19.56 88.9,19.56 91.69,22.35 102.36,22.35 J5.11 | v62.74,29.21 62.74,37.34 50.04,50.04 v50.04,51.82
SDA  (via drill 0.3)
  Top 0.254: U7.29 15.63,41.54 v15.49,41.4 | v10.67,32.26 9.91,31.5 v7.11,31.5 7.62,30.99 7.62,30.73 7.33,30.44 U12.5 5.12,30.44 4.57,30.99 2.79,30.99 2.29,30.49 R53.2 | v7.37,24.89 7.62,25.15 9.4,25.15 10.41,24.13 10.41,23.37 13.18,20.61 U10.10
  Bottom 0.254: v15.49,41.4 14.99,41.4 12.19,38.61 12.19,32.77 12.45,32.51 12.45,32 11.94,31.5 11.43,31.5 v10.67,32.26 | v7.11,31.5 7.37,31.24 v7.37,24.89
SIMO  (via drill 0.3)
  Top 0.254: v61.98,28.19 62.48,27.69 62.48,24.64 68.07,19.05 76.45,19.05 78.23,20.83 v78.23,21.59 78.01,21.81 U1.46 | X1.3 51.37,63.31 v51.31,63.25 | v43.69,61.98 40.39,58.67 40.39,55.63 41.24,54.77 U3.24 | J5.10 105.16,27.69 105.16,30.23 J5.5
  Bottom 0.254: v51.31,63.25 51.31,63.75 50.8,64.26 45.97,64.26 v43.69,61.98 | v78.23,21.59 78.23,21.34 78.99,20.57 88.39,20.57 91.19,23.37 100.1,23.37 102.62,25.88 102.62,30.23 J5.5 | U3.24 42.34,53.09 45.97,53.09 61.98,37.08 v61.98,28.19
SOMI  (via drill 0.3)
  Top 0.254: v78.74,22.35 78.51,22.58 U1.47 | v76.2,21.84 75.44,21.08 67.56,21.08 64.01,24.64 64.01,29.72 v63.5,30.23 | X1.7 55.77,55.52 55.12,54.86 v55.12,46.23 | J5.12 105.16,25.15 103.12,25.15 102.62,25.65 102.62,32.77 J5.3
  Bottom 0.254: v76.2,21.84 76.71,22.35 v78.74,22.35 80.01,21.08 88.14,21.08 90.93,23.88 99.87,23.88 101.85,25.86 101.85,31.24 103.89,33.27 J5.3 | v63.5,30.23 63.5,37.85 v55.12,46.23
TCK  (via drill 0.3)
  Top 0.254: U1.75 88.36,34.51 92.71,38.86 98.81,38.86 105.41,45.47 v105.41,45.72
  Bottom 0.254: v105.41,45.72 106.43,45.72 107.19,46.48 107.19,53.34 J1.7
TDI
  Top 0.254: U1.73 88.88,33.51 93.22,37.85 99.31,37.85 107.44,45.97 107.44,48.77 108.2,49.53 J1.3
TDO
  Top 0.254: U1.72 89.14,33.01 93.47,37.34 99.57,37.34 108.46,46.23 J1.1
TEST  (via drill 0.3)
  Top 0.254: v75.95,30.73 75.69,30.99 75.69,36.58 73.66,38.61 71.37,38.61 70.87,38.1 64.26,38.1 v64.01,38.35 | JP16.1 23.62,45.72 29.21,40.13 v62.23,40.13 | J1.8 107.19,53.34 108.71,53.34 109.73,52.32 109.73,46.74 99.82,36.83 93.73,36.83 89.4,32.51 U1.71 85.09,32.51 v84.07,31.5
  Bottom 0.254: v75.95,30.73 83.31,30.73 v84.07,31.5 | v62.23,40.13 v64.01,38.35
TMS
  Top 0.254: U1.74 87.12,34.04 88.65,34.04 92.96,38.35 99.06,38.35 106.93,46.23 106.93,50.55 J1.5
TXD  (via drill 0.3)
  Top 0.254: U1.51 80.51,27.43 81.28,28.19 81.28,33.78 78.99,36.07 v78.99,36.83 | JP16.7 23.88,53.34 31.75,45.47 v47.24,45.47 57.4,45.47 62.99,51.05 68.83,51.05 75.95,58.17 75.95,60.2 76.45,60.71 77.72,60.71 78.23,61.21 78.23,63.5 J12.5 | v50.29,30.23 50.29,37.85 v49.53,38.61 | J4.12 88.65,62.99 84.33,62.99 83.82,62.48 83.31,62.48 v82.55,63.25 82.55,69.03 83.12,69.6 J4.5
  Bottom 0.254: v78.99,36.83 78.99,37.08 81.53,39.62 82.3,39.62 83.57,40.89 83.57,62.23 v82.55,63.25 82.3,63.5 78.23,63.5 J12.5 | CON1.5 50.97,30.23 v50.29,30.23 | v49.53,38.61 47.24,40.89 v47.24,45.47 | J13.1 85.85,79.12 85.85,70.36 86.61,69.6 J4.5
UCTS
  Top 0.254: U7.18 17.81,36.04 18.03,35.81 18.03,34.29 17.02,33.27 17.02,30.99 14.99,28.96 14.99,23.37 14.62,23.01 U10.13
UDSR
  Top 0.254: U7.17 16.76,35.5 16.76,34.04 16.51,33.78 16.51,31.24 14.22,28.96 14.22,27.43 12.7,25.91 12.7,24.13 13.02,23.81 U10.14
UDTR
  Top 0.254: U7.16 14.75,32.28 13.97,31.5 11.68,31.5 9.25,29.06 U10.21
URTS  (via drill 0.3)
  Top 0.254: U7.15 14.25,32.54 13.97,32.26 v13.46,32.26 | U10.20 10.05,27.83 v10.41,28.19
  Bottom 0.254: v13.46,32.26 11.43,30.23 11.43,29.21 v10.41,28.19
URXD
  Top 0.254: U7.33 14.75,43.71 14.22,43.18 14.22,35.81 15.49,34.54 15.49,31.75 13.21,29.46 13.21,28.45 12.7,27.94 11.18,27.94 10.85,27.62 U10.19
UTXD
  Top 0.254: U7.32 16.76,43.04 16.76,43.43 15.24,43.43 14.73,42.93 14.73,36.07 16,34.8 16,31.5 13.72,29.21 13.72,28.19 12.45,26.93 U10.17
V18
  Top 0.254: U1.67 85.12,30.51 84.07,29.46 84.07,28.19 87.63,24.64 C8.1
VCC  (via drill 0.3, 0.56)
  Top 0.254: C19.2 52.47,61.75 | U5.9 24.14,33.79
  Top 0.406: 25.65,36.32 25.65,35.31 24.14,33.79 | 25.65,36.32 C30.2 | 25.65,36.32 v27.43,36.32
  Top 0.61: C24.2 43.78,56.98 U3.23 | U3.22 46.32,57.13 C23.2 46.23,57.23 46.23,59.44 v46.48,59.69 47.16,60.36 R6.1 | v28.96,57.15 R18.1 30.65,58.33 v30.99,58.67 | C19.2 52.5,61.14 v51.31,59.94 | C18.2 56.97,60.63 v58.17,59.44 | R17.1 36.41,58.08 v35.81,58.67 | 52.47,61.75 52.47,63.14 v52.58,63.25 52.47,63.35 X1.4
  Top 1.016: v98.55,49.02 95.5,49.02 89.92,54.61 v89.92,56.64
  PWR 0.813: v28.96,57.15 27.69,55.88 27.69,36.58 v27.43,36.32
  PWR 1.016: v58.17,59.44 60.71,56.9 64.77,56.9 66.55,55.12 JP14.1 77.22,56.64 77.98,57.4 86.61,57.4 | J4.1 85.09,72.64 85.09,58.93 86.61,57.4 | 86.61,57.4 89.15,57.4 v89.92,56.64 | v98.55,49.02 99.06,49.02 103.89,44.2 J5.1
  Bottom 0.813: CON2.4 CON2.2 26.38,34.5 26.38,35.27 v27.43,36.32
  pour PWR (isolate 0.406): 26.67,52.58 26.67,73.66 32.26,73.66 40.64,65.28 59.44,65.28 59.44,52.58
VCC_SW
  Top 1.27: J9.1 13.68,77.72 17.02,77.72 | 17.02,77.72 J10.3 21.59,77.72 JP7.1 | SW1.3 8.48,70.2 9.4,71.12 15.75,71.12 17.02,72.39 17.02,77.72
VCORE
  Top 0.305: U1.20 75.51,39.8 75.18,40.13 74.17,40.13 72.39,41.91 TP2.1 71.69,41.47 C17.2
VLCD
  Top 0.254: U3.15 63.93,54.35 C22.1
VREF+
  Top 0.254: U1.9 81.01,42.39 83.58,44.96 C14.2 83.73,45.63 86.81,48.7 TP1.1
XIN  (via drill 0.3)
  Top 0.254: v80.77,44.2 79.56,44.2 Q1.P2 79.51,44.24 U1.12
  Bottom 0.254: C2.1 80.44,44.53 v80.77,44.2
XIN1
  Top 0.254: U7.52 6.23,41.54 6.35,41.66 6.35,44.45 5.08,45.72 5.08,48.26 5.84,49.02 6.56,49.02 Q3.P$3 C39.1
XOUT  (via drill 0.3)
  Top 0.254: 76.9,44.2 v75.69,44.2 | 76.9,44.2 Q1.P1 | 76.9,44.2 76.9,43.24 77.47,42.67 78.49,42.67 79.01,42.14 U1.13
  Bottom 0.254: C4.1 76.02,44.53 v75.69,44.2
XOUT1
  Top 0.254: U7.53 4.17,41.04 4.06,41.15 4.06,44.45 4.32,44.7 C38.1 4.31,45.77 Q3.P$1
XT2GND  (via drill 0.56)
  Top 0.305: 87.2,31.01 89.89,31.01 v90.42,30.48
  other vias: 93.98,35.31 93.98,27.69
  pour Bottom (isolate 0.254): 86.36,30.48 arc90 86.61,30.23 87.78,30.23 arc-45 89.69,29.44 91.53,27.59 arc45 94.98,26.16 95,26.16 arc90 97.28,28.45 97.28,34.8 arc90 95.25,36.83 95.02,36.83 arc45 91.07,35.19 89.68,33.8 arc-45 88.41,33.27 86.61,33.27 arc90 86.36,33.02
  pour GND (isolate 0.254): 86.36,30.48 arc90 86.61,30.23 87.78,30.23 arc-45 89.69,29.44 91.53,27.59 arc45 94.98,26.16 95,26.16 arc90 97.28,28.45 97.28,34.8 arc90 95.25,36.83 95.02,36.83 arc45 91.07,35.19 89.68,33.8 arc-45 88.41,33.27 86.61,33.27 arc90 86.36,33.02
  pour Top (isolate 0.254): 86.36,30.48 arc90 86.61,30.23 87.78,30.23 arc-45 89.69,29.44 91.53,27.59 arc45 94.98,26.16 95,26.16 arc90 97.28,28.45 97.28,34.8 arc90 95.25,36.83 95.02,36.83 arc45 91.07,35.19 89.68,33.8 arc-45 88.41,33.27 86.61,33.27 arc90 86.36,33.02
XT2IN
  Top 0.305: U1.69 90.67,31.51 93.12,29.06 Q2.1 Q2.1.1
  Bottom 0.305: C6.1 94.33,29.72 Q2.1
XT2OUT
  Top 0.305: U1.70 90.68,32.01 92.61,33.94 Q2.2 Q2.2.1
  Bottom 0.305: C1.1 94.33,33.27 Q2.2

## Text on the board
Top: T
GND: G
PWR: P
Bottom: B
tNames: microSD | GND | 430 | PWR | 2.6 | 3.0 | 5529 | USB | GND | Vcc | 3.2 | Target | LDO | 3.1 | GND | 2.1 | SYS | PWR | 2.3 | VCC | 6.6 | BSL | eZ | GND | GND | EXT BATT | 7.5 | 4.5 | 8.1 | - | > | 2.4 | JTAG | 5529 | 4.7 | 8.2 | POWER SEL | 4.4 | BATT | 4.6 | USB | LDO | 4.5 | 4.6 | 8.0 | - | < | 4.0 | ALT | 4.4 | 4.5 | INT | 4.7 | 2.0 | PWR | JTAG | 1.0 | 5.1 | 4.4 | RST | 5529 | GND | PWR | 6.7 | EXT | GND | > | eZ-RF | > | - | - | DVCC | RF | PWR | TXD | eZ430 | Target | TXS0104E | RXD | RST | TEST | MSP430F5529 | JTAG | VCC | 7.0 | 4.2 | 7.1 | 4.1 | 7.2 | TPS75105 | 4.3 | 7.3 | 4.0 | 4.1 | 3.7 | 4.2 | ACCEL. | Rev | 2.0 | GND | 7.7 | MSP-EXP430F5529 | MSP-EXP430F5529 | LED1 | POT | eZ430-EMULATION | LEDs | 1 | POT1 | 2 | 3 | eZPWR | eZ | USB | GND | GND
bNames: FOOT | FOOT | FOOT | FOOT | RoHS
Measures: 3.2 in (81.28 mm) | 4.4 in (111.76 mm)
